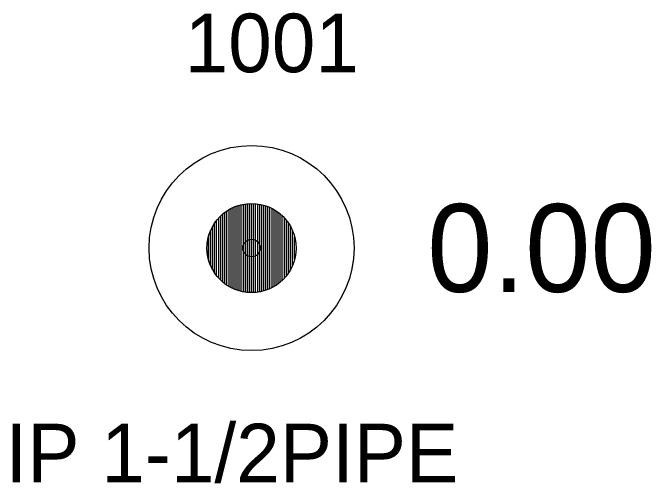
# Model space of a CAD drawing. Extents: x 2374510 to 2377726, y 1024129 to 1025429.
# Drawn here: x 2374510.22 to 2374521.12, y 1024128.94 to 1024136.97 of the extents above; entities that cross this region are included whole.
import ezdxf

# ---------------------------------------------------------------- set-up
doc = ezdxf.new("R2010")
doc.units = 0
for name, color, linetype in [('RD_EX_DV_Prop_txCode', 7, 'Continuous'), ('RD_EX_DV_PropPin', 7, 'Continuous'), ('RD_EX_TX_DV_Prop_ELEV', 7, 'Continuous'), ('RD_SMD_Locator', 7, 'Continuous')]:
    doc.layers.add(name, color=color, linetype=linetype)

msp = doc.modelspace()

# ---------------------------------------------------------------- linework, layer by layer
at = {"layer": 'RD_EX_DV_PropPin'}
for p, q in [((2374514.018, 1024132.243), (2374514.018, 1024133.658)), ((2374514.053, 1024132.23), (2374514.053, 1024133.671)), ((2374514.088, 1024132.219), (2374514.088, 1024133.682)), ((2374514.123, 1024132.21), (2374514.123, 1024133.691)), ((2374514.158, 1024132.202), (2374514.158, 1024133.699)), ((2374514.193, 1024132.197), (2374514.193, 1024133.704)), ((2374514.228, 1024132.193), (2374514.228, 1024133.708)), ((2374514.263, 1024132.19), (2374514.263, 1024133.711)), ((2374514.298, 1024132.189), (2374514.298, 1024133.712)), ((2374514.333, 1024132.19), (2374514.333, 1024133.711)), ((2374514.368, 1024132.193), (2374514.368, 1024133.708)), ((2374514.403, 1024132.197), (2374514.403, 1024133.704)), ((2374514.438, 1024132.202), (2374514.438, 1024133.699)), ((2374514.473, 1024132.21), (2374514.473, 1024133.691)), ((2374514.508, 1024132.219), (2374514.508, 1024133.682)), ((2374514.543, 1024132.23), (2374514.543, 1024133.671)), ((2374514.578, 1024132.243), (2374514.578, 1024133.658)), ((2374513.842, 1024132.341), (2374513.842, 1024133.56)), ((2374513.878, 1024132.316), (2374513.878, 1024133.585)), ((2374513.913, 1024132.294), (2374513.913, 1024133.607)), ((2374513.948, 1024132.275), (2374513.948, 1024133.626)), ((2374513.983, 1024132.258), (2374513.983, 1024133.643)), ((2374514.613, 1024132.258), (2374514.613, 1024133.643)), ((2374514.648, 1024132.275), (2374514.648, 1024133.626)), ((2374514.683, 1024132.294), (2374514.683, 1024133.607)), ((2374514.718, 1024132.316), (2374514.718, 1024133.585)), ((2374514.753, 1024132.341), (2374514.753, 1024133.56)), ((2374513.737, 1024132.435), (2374513.737, 1024133.466)), ((2374513.772, 1024132.4), (2374513.772, 1024133.501)), ((2374513.807, 1024132.368), (2374513.807, 1024133.533)), ((2374514.788, 1024132.368), (2374514.788, 1024133.533)), ((2374514.823, 1024132.4), (2374514.823, 1024133.501)), ((2374514.858, 1024132.435), (2374514.858, 1024133.466)), ((2374513.667, 1024132.524), (2374513.667, 1024133.377)), ((2374513.702, 1024132.476), (2374513.702, 1024133.425)), ((2374514.893, 1024132.476), (2374514.893, 1024133.425)), ((2374514.928, 1024132.524), (2374514.928, 1024133.377)), ((2374513.597, 1024132.653), (2374513.597, 1024133.248)), ((2374513.632, 1024132.581), (2374513.632, 1024133.32)), ((2374514.963, 1024132.581), (2374514.963, 1024133.32)), ((2374514.998, 1024132.653), (2374514.998, 1024133.248)), ((2374513.562, 1024132.754), (2374513.562, 1024133.147)), ((2374515.033, 1024132.754), (2374515.033, 1024133.147))]:
    msp.add_line(p, q, dxfattribs=at)
for radius in [1.75, 0.761]:
    msp.add_circle((2374514.298, 1024132.95), radius, dxfattribs=at)
at = {"layer": 'RD_SMD_Locator'}
msp.add_circle((2374514.298, 1024132.95), 0.15, dxfattribs=at)

# ---------------------------------------------------------------- texts
at = {"layer": 'RD_EX_DV_Prop_txCode'}
for s, p in [('1001', (2374513.156, 1024135.951)), ('IP 1-1/2PIPE', (2374510.097, 1024128.951))]:
    msp.add_text(s, height=1, dxfattribs=at).set_placement(p)
at = {"layer": 'RD_EX_TX_DV_Prop_ELEV'}
msp.add_text('0.00', height=1.5, dxfattribs=at).set_placement((2374517.298, 1024132.201))

doc.saveas('drawing.dxf')
